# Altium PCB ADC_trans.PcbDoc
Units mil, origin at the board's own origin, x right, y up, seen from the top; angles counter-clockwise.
Board outline 1035 x 2320 mil, 2 copper layers (Top Layer, Bottom Layer); 2 components, 36 nets, 80 pads, 0 vias.
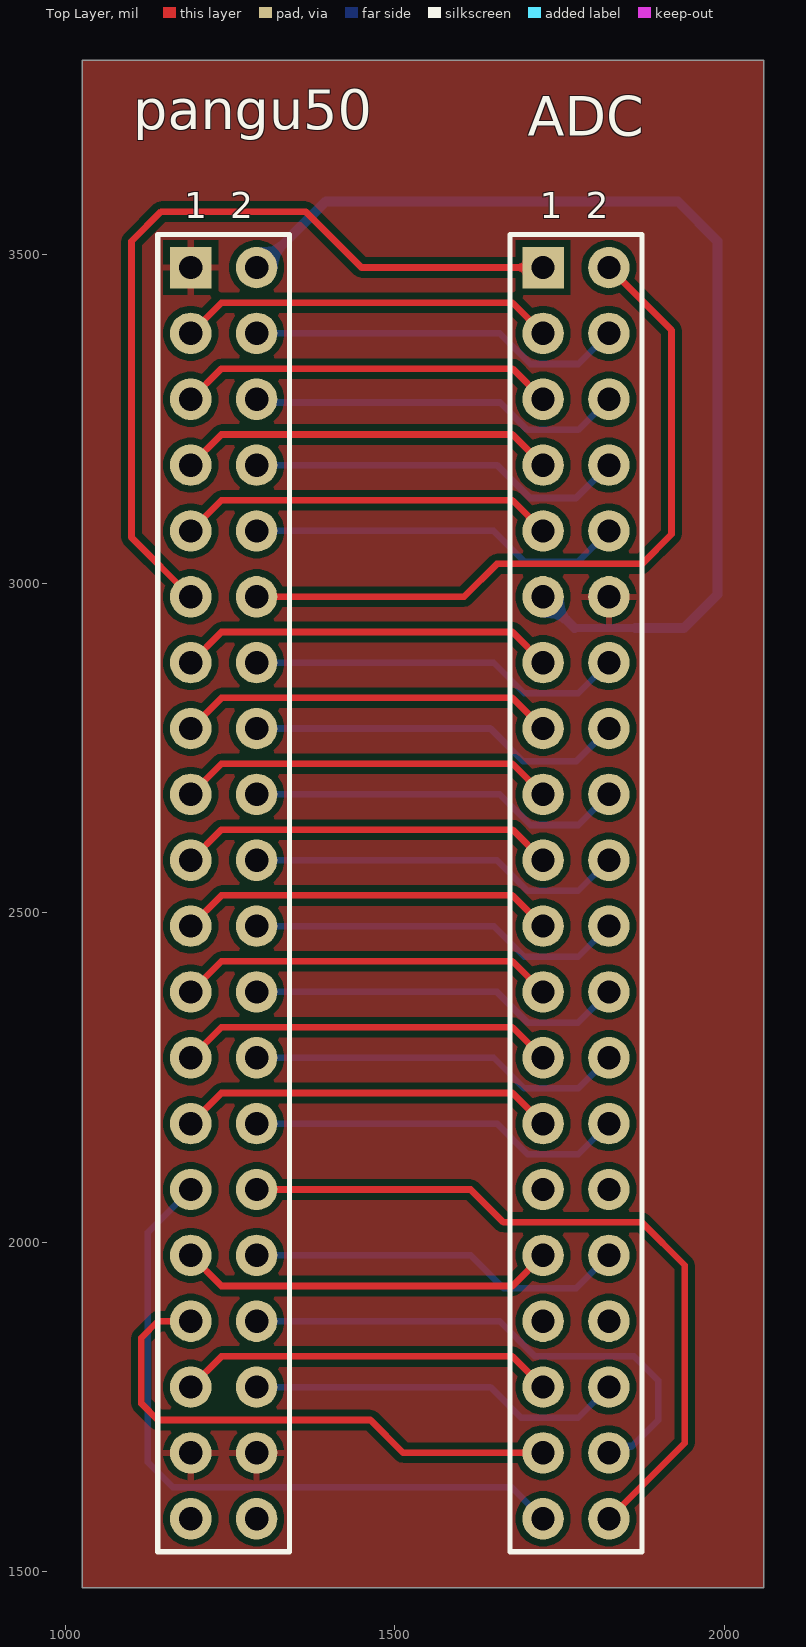
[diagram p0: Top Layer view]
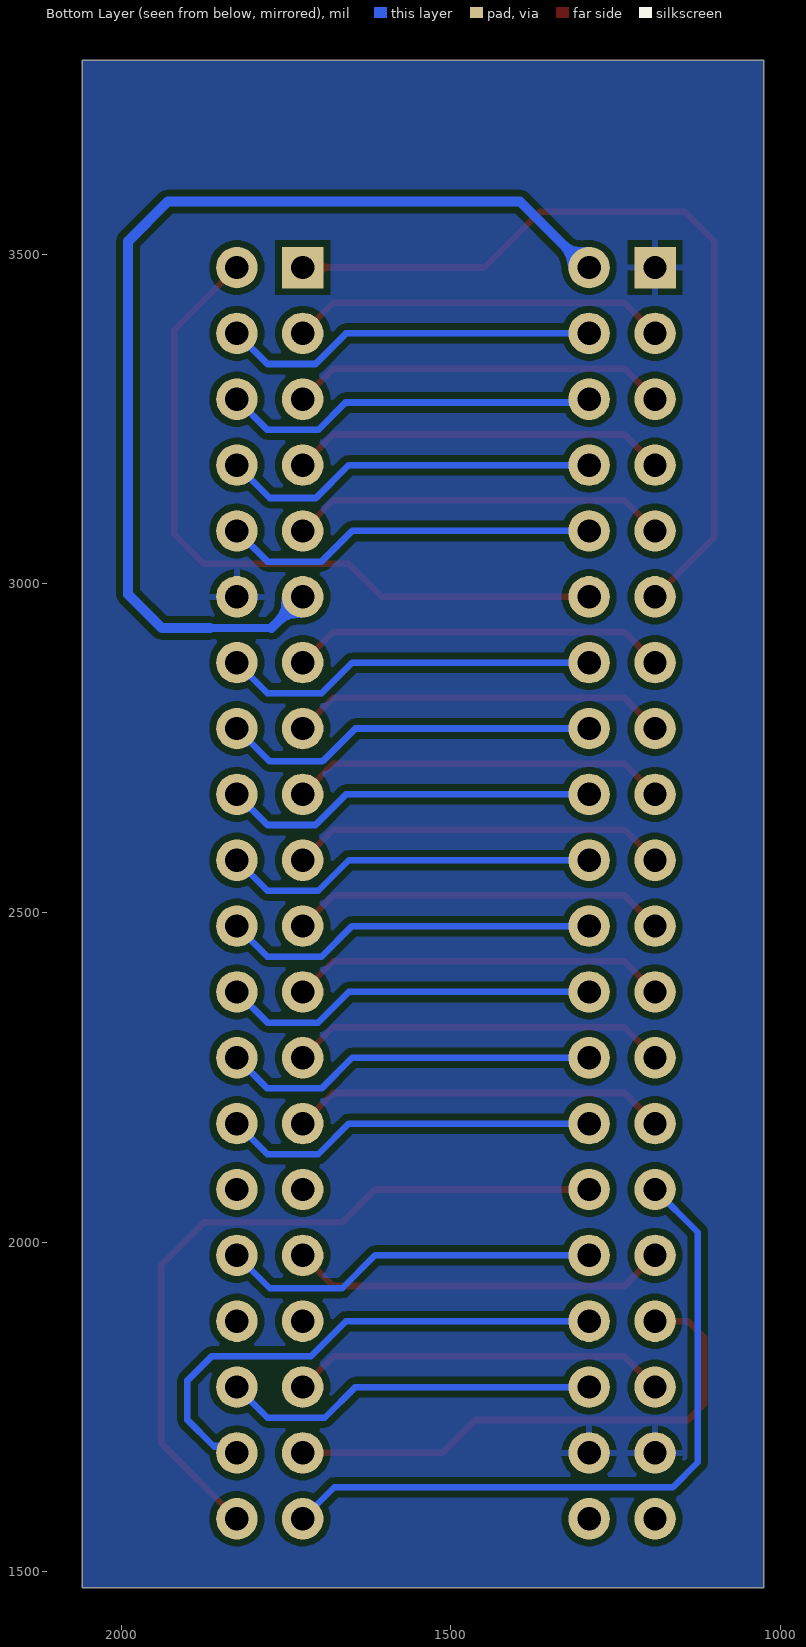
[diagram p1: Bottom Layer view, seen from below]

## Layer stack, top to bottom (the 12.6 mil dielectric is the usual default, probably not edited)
Top Solder: solder mask 0.4, Solder Resist, Dk 3.5
Top Layer: signal copper 1.4
Dielectric 1: dielectric 12.6, FR-4, Dk 4.8
Bottom Layer: signal copper 1.4
Bottom Solder: solder mask 0.4, Solder Resist, Dk 3.5

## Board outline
1025,1475 1025,3795 2060,3795 2060,1475

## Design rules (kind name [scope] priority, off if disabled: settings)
Clearance [All] p1: gap=10 ignorepadtopadclearanceinfootprint=FALSE except(0: Arc-Hole Track-Hole SMDPad-Hole THPad-Hole Via-Hole Fill-Hole Poly-Hole Region-Hole Text-Hole)
PolygonConnect [All] p1: connectstyle=Relief reliefconductorwidth=10 reliefentries=4 polygonreliefangle="90 Angle" airgapwidth=10
RoutingVias [All] p1: holewidth=28 width=50 viastyle="Through Hole" minholewidth=28 minwidth=50 maxholewidth=28 maxwidth=50
SolderMaskExpansion [All] p1: expansion=4 istentingtop=FALSE
UnRoutedNet [All] p1: checkbadconnections=TRUE
Width [All] p1: maxlimit=20 minlimit=10 preferedwidth=10
29 further rules are at their usual default settings.

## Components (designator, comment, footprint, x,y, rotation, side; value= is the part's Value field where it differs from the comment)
ADC "Header 2X20" "Header 2.54 2X20P" 1725,3480 r270 top
pangu50 "Header 2X20" "Header 2.54 2X20P" 1190,3480 r270 top

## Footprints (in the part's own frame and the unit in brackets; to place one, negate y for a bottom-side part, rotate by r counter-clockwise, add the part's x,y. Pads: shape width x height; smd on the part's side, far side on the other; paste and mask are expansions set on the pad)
"Header 2.54 2X20P" [mm]
  rect 1.6x1.6 hole 0.9: 1(0,0)
  round 1.6 hole 0.9: 2(0,2.54) 3(2.54,0) 4(2.54,2.54) 5(5.08,0) 6(5.08,2.54) 7(7.62,0) 8(7.62,2.54) 9(10.16,0) 10(10.16,2.54) 11(12.7,0) 12(12.7,2.54) 13(15.24,0) 14(15.24,2.54) 15(17.78,0) 16(17.78,2.54) 17(20.32,0) 18(20.32,2.54) 19(22.86,0) 20(22.86,2.54) 21(25.4,0) 22(25.4,2.54) 23(27.94,0) 24(27.94,2.54) 25(30.48,0) 26(30.48,2.54) 27(33.02,0) 28(33.02,2.54) 29(35.56,0) 30(35.56,2.54) 31(38.1,0) 32(38.1,2.54) 33(40.64,0) 34(40.64,2.54) 35(43.18,0) 36(43.18,2.54) 37(45.72,0) 38(45.72,2.54) 39(48.26,0) 40(48.26,2.54)
  silkscreen extent -1.27,-1.27 49.53,3.81

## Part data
ADC pangu50: library part "Header 20X2", "20*2P接插件"

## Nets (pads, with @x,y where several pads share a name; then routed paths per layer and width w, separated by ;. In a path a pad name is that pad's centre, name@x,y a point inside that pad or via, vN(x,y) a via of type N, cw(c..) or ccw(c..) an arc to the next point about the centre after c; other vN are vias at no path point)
EX_IO_1N: ADC.35 pangu50.35 | length 573.5
  Top Layer w10: pangu50.35 1236.5,1826.5 1678.5,1826.5 ADC.35
EX_IO_1P: ADC.36 pangu50.36 | length 573.5
  Bottom Layer w10: pangu50.36 1645,1780 1691.5,1733.5 1778.5,1733.5 ADC.36
EX_IO_2N: ADC.37 pangu50.33 | length 826.4
  Top Layer w10: pangu50.33 1140,1880 1115,1855 1115,1755 1140,1730 1462.83,1730 1512.83,1680 ADC.37
EX_IO_2P: ADC.38 pangu50.34 | length 803
  Bottom Layer w10: pangu50.34 1659.24,1880 1712.75,1826.5 1863.5,1826.5 1900,1790 1900,1730 1860.14,1690.14 1835.14,1690.14 ADC.38
EX_IO_3N: ADC.25 pangu50.25 | length 573.5
  Top Layer w10: pangu50.25 1236.5,2326.5 1678.5,2326.5 ADC.25
EX_IO_3P: ADC.26 pangu50.26 | length 573.5
  Bottom Layer w10: pangu50.26 1650,2280 1696.5,2233.5 1778.5,2233.5 ADC.26
EX_IO_4N: ADC.27 pangu50.27 | length 573.5
  Top Layer w10: pangu50.27 1236.5,2226.5 1678.5,2226.5 ADC.27
EX_IO_4P: ADC.28 pangu50.28 | length 573.5
  Bottom Layer w10: pangu50.28 1655,2180 1701.5,2133.5 1778.5,2133.5 ADC.28
EX_IO_5N: ADC.31 pangu50.31 | length 573.5
  Top Layer w10: pangu50.31 1236.5,1933.5 1678.5,1933.5 ADC.31
EX_IO_5P: ADC.32 pangu50.32 | length 576.4
  Bottom Layer w10: pangu50.32 1615,1980 1665,1930 1775,1930 ADC.32
EX_IO_6N: ADC.39 pangu50.29 | length 1076.6
  Bottom Layer w10: pangu50.29 1125,2015 1125,1665.86 1162.86,1628 1677,1628 ADC.39
EX_IO_6P: ADC.40 pangu50.30 | length 1130.3
  Top Layer w10: pangu50.30 1615,2080 1665,2030 1875,2030 1940,1965 1940,1695 ADC.40
EX_IO_7N: ADC.15 pangu50.15 | length 573.5
  Top Layer w10: pangu50.15 1236.5,2826.5 1678.5,2826.5 ADC.15
EX_IO_7P: ADC.16 pangu50.16 | length 576.4
  Bottom Layer w10: pangu50.16 1645,2780 1695,2730 1775,2730 ADC.16
EX_IO_8N: ADC.17 pangu50.17 | length 573.5
  Top Layer w10: pangu50.17 1236.5,2726.5 1678.5,2726.5 ADC.17
EX_IO_8P: ADC.18 pangu50.18 | length 573.5
  Bottom Layer w10: pangu50.18 1659.24,2680 1705.74,2633.5 1778.5,2633.5 ADC.18
EX_IO_9N: ADC.5 pangu50.5 | length 573.5
  Top Layer w10: pangu50.5 1236.5,3326.5 1678.5,3326.5 ADC.5
EX_IO_9P: ADC.6 pangu50.6 | length 573.5
  Bottom Layer w10: pangu50.6 1295,3275 1660,3275 1701.5,3233.5 1778.5,3233.5 ADC.6
EX_IO_10N: ADC.7 pangu50.7 | length 573.5
  Top Layer w10: pangu50.7 1236.5,3226.5 1678.5,3226.5 ADC.7
EX_IO_10P: ADC.8 pangu50.8 | length 590.8
  Top Layer w10: pangu50.8 pangu50.8@1300.14,3169.86
  Bottom Layer w10: pangu50.8 1655,3180 1705,3130 1775,3130 ADC.8
EX_IO_11N: ADC.3 pangu50.3 | length 573.5
  Top Layer w10: pangu50.3 1236.5,3426.5 1678.5,3426.5 ADC.3
EX_IO_11P: ADC.4 pangu50.4 | length 573.5
  Bottom Layer w10: pangu50.4 1659.24,3380 1705.74,3333.5 1778.5,3333.5 ADC.4
EX_IO_12N: ADC.9 pangu50.9 | length 573.5
  Top Layer w10: pangu50.9 1236.5,3126.5 1678.5,3126.5 ADC.9
EX_IO_12P: ADC.10 pangu50.10 | length 587.9
  Top Layer w10: pangu50.10 pangu50.10@1304.34,3080
  Bottom Layer w10: pangu50.10 1650,3080 1696.5,3033.5 1778.5,3033.5 ADC.10
EX_IO_13N: ADC.21 pangu50.21 | length 573.5
  Top Layer w10: pangu50.21 1236.5,2526.5 1678.5,2526.5 ADC.21
EX_IO_13P: ADC.22 pangu50.22 | length 573.5
  Bottom Layer w10: pangu50.22 1650,2480 1696.5,2433.5 1778.5,2433.5 ADC.22
EX_IO_14N: ADC.19 pangu50.19 | length 573.5
  Top Layer w10: pangu50.19 1236.5,2626.5 1678.5,2626.5 ADC.19
EX_IO_14P: ADC.20 pangu50.20 | length 573.5
  Bottom Layer w10: pangu50.20 1655,2580 1701.5,2533.5 1778.5,2533.5 ADC.20
EX_IO_15N: ADC.1 pangu50.11 | length 1256.1
  Top Layer w10: pangu50.11 1100,3070 1100,3520 1145,3565 1364.25,3565 1449.25,3480 ADC.1
EX_IO_15P: ADC.2 pangu50.12 | length 1113.7
  Top Layer w10: pangu50.12 1605,2980 1655,3030 1875,3030 1920,3075 1920,3385 ADC.2
EX_IO_16N: ADC.13 pangu50.13 | length 573.5
  Top Layer w10: pangu50.13 1236.5,2926.5 1678.5,2926.5 ADC.13
EX_IO_16P: ADC.14 pangu50.14 | length 573.5
  Bottom Layer w10: pangu50.14 1650,2880 1696.5,2833.5 1778.5,2833.5 ADC.14
EX_IO_17N: ADC.23 pangu50.23 | length 573.5
  Top Layer w10: pangu50.23 1236.5,2426.5 1678.5,2426.5 ADC.23
EX_IO_17P: ADC.24 pangu50.24 | length 573.5
  Bottom Layer w10: pangu50.24 1655,2380 1701.5,2333.5 1778.5,2333.5 ADC.24
GND: ADC.12 pangu50.1 pangu50.37 pangu50.38
VCC5: ADC.11 pangu50.2 | length 1608.6
  Bottom Layer w12: 1772.5,2932.5 1805.33,2932.5 1865.42,2932.5
  Bottom Layer w15: pangu50.2 1295,3480 1395,3580 1930,3580 1990,3520 1990,2983.5 1939,2932.5 1865.42,2932.5 ; ADC.11 1772.5,2932.5
pads on no net: ADC.29 ADC.30 ADC.33 ADC.34 pangu50.39 pangu50.40

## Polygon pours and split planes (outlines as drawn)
GND on Bottom Layer "GND_L02_P001" (solid, pour order 1): 1025,3795 2060,3795 2060,1475 1025,1475
GND on Top Layer "GND_L01_P002" (solid, pour order 2): 1025,3795 2060,3795 2060,1475 1025,1475

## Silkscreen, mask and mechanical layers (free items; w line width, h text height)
Top Overlay:
  text "1  2" at 1180,3555 h40
  text "1  2" at 1720,3555 h40
Mechanical 1:
  the board outline again, w10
